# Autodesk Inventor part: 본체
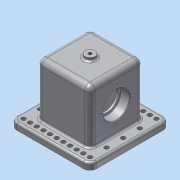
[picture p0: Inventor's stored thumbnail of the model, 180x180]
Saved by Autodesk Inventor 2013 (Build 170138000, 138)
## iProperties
Created: 2018-11
Part Number: 본체
Material: 알루미늄 6061
Document SubType Name: Modeling
Designer: dgall
Density: 2.71 g/cm^3
Mass: 1020.76 g
Surface Area: 777.082 cm^2
Volume: 376.663 cm^3
Author: dgall
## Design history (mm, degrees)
sketch "스케치1"
  geometry: L1 (0.533, -0.244)-(80.533, -0.244); L2 (80.533, -0.244)-(80.533, 79.756); L3 (80.533, 79.756)-(0.533, 79.756); L4 (0.533, 79.756)-(0.533, -0.244); 1 further point
  constraints: 8 end point, 2 parallel, 2 perpendicular, 1 horizontal
  dimensions: "d0" = 80 distance of L2.end L3.end
extrude "돌출1" new body sketch "스케치1" distance "d2" = 90; taper "d3" = 0 deg
sketch "스케치2"
  geometry: L1 (-0.533, -0.244)-(-0.533, 79.756) reference; L2 (-0.533, 79.756)-(-80.533, 79.756) reference; L3 (-100.533, -20.244)-(19.467, -20.244); L4 (19.467, -20.244)-(19.467, 99.756); L5 (19.467, 99.756)-(-100.533, 99.756); L6 (-100.533, 99.756)-(-100.533, -20.244); 5 further points
  constraints: 8 end point, 4 midpoint, 2 parallel, 2 perpendicular, 1 horizontal, 1 horizontal alignment, 1 vertical alignment
  dimensions: "d4" = 120 distance of L4.end L5.end
extrude "돌출2" join sketch "스케치2" distance "d6" = 10; taper "d7" = 0 deg
sketch "스케치3"
  geometry: L1 (19.467, -20.244)-(19.467, 99.756) reference; L2 (19.467, 99.756)-(-100.533, 99.756) reference; L3 (-63.533, 9.756)-(-17.533, 9.756); L4 (-17.533, 9.756)-(-17.533, 69.756); L5 (-17.533, 69.756)-(-63.533, 69.756); L6 (-63.533, 69.756)-(-63.533, 9.756); L7 (-100.533, -20.244)-(19.467, -20.244) reference; L8 (19.467, -20.244)-(19.467, 99.756) reference; L9 (19.467, 99.756)-(-100.533, 99.756) reference; L10 (-100.533, 99.756)-(-100.533, -20.244) reference; 5 further points
  constraints: 8 end point, 4 midpoint, 2 parallel, 1 horizontal, 1 horizontal alignment, 1 perpendicular, 1 vertical alignment
  dimensions: "d8" = 46 distance of L4.end L5.end; "d10" = 60 distance of L3.end L4.end
extrude "돌출3" cut sketch "스케치3" distance "d11" = 80; taper "d12" = 0 deg
sketch "스케치4"
  geometry: L1 (0, 0)-(0, 80) reference; L2 (80, 0)-(80, 80) reference; L3 (0, 80)-(80, 80) reference; L4 (0, 0)-(0, 80) reference; L5 (0, 0)-(80, 0) reference; L6 (90, 100)-(90, -20) reference; C1 r 20 at (42, 40); 2 further points
  constraints: 1 centre point, 1 horizontal alignment, 1 midpoint
  dimensions: "d13" = 48 distance from line of L6 C1.centre; "d14" = 40 diameter of C1
extrude "돌출4" cut sketch "스케치4" distance "d15" = 14; taper "d16" = 0 deg
sketch "스케치5"
  geometry: C1 r 20 at (0, 0) reference; C2 r 16.5 at (0, 0); 1 further point
  constraints: 1 centre point, 1 coincident
  dimensions: "d17" = 33 diameter of C2
extrude "돌출5" cut sketch "스케치5" distance "d19" = 17; taper "d20" = 0 deg
node "작업 평면1"
sketch "스케치6"
  geometry: L1 (0.533, -0.244)-(80.533, -0.244) reference; L2 (80.533, -0.244)-(80.533, 79.756) reference; L3 (80.533, 79.756)-(0.533, 79.756) reference; L4 (0.533, 79.756)-(0.533, -0.244) reference; C1 r 7.5 at (40.533, 39.756); 3 further points
  constraints: 2 midpoint, 1 centre point, 1 horizontal alignment, 1 vertical alignment
  dimensions: "d22" = 15 diameter of C1
extrude "돌출6" join sketch "스케치6" stored distance "d24" = 17; taper "d25" = 0 deg
node "작업 평면2"
fillet "모깎기1" dims "d26" = 10
sketch "스케치7"
  geometry: C1 r 3.3 at (-9.467, 89.756); A1 r 10 centre (-9.467, 89.756) between (-9.467, 99.756) and (-19.467, 89.756) reference; 1 further point
  constraints: 1 centre point, 1 coincident
  dimensions: "d27" = 6.6 diameter of C1
extrude "돌출7" cut sketch "스케치7" distance "d30" = 17; taper "d31" = 0 deg
node "작업 평면3"
fillet "모깎기2" dims "d38" = 8
fillet "모깎기3" dims "d39" = 3
fillet "모깎기4" dims "d40" = 3
hole "구멍1" diameter "d43" = 4.917; stored, may be unused: countersink angle "d47" = 90 deg, drill point angle "d49" = 118 deg; dims "d41" = 10, "d42" = 10, "d44" = 6, "d45" = 4, "d46" = 2, "d48" = 8
sketch "스케치8" dims "d50" = 52
  geometry: C1 r 20 at (-34, 32) reference; 3 further points
  constraints: 2 horizontal alignment, 1 coincident, 2 other
hole "구멍2" sketch "스케치8" at (-8, 32) diameter "d52" = 3.242; stored, may be unused: countersink angle "d56" = 90 deg, drill point angle "d58" = 118 deg; dims "d53" = 8, "d54" = 4, "d55" = 2, "d57" = 10
node "작업 평면4"
sketch "스케치9"
  geometry: L1 (-18, 82)-(82, 82) reference; L2 (0, 69)-(64, 69) reference; L3 (0, 0)-(0, 69) reference; L4 (64, 0)-(0, 0) reference; L5 (64, 69)-(64, 0) reference; 3 further points
  constraints: 1 midpoint, 1 vertical alignment, 1 other
  dimensions: "d63" = 48 distance from line of L1 point (32, 34)
feature "엠보싱1" sketch "스케치9" dims "d0" = 80, "d64" = 0.5, "d65" = 0
fillet "모깎기5" dims "d66" = 3
fillet "모깎기6" dims "d67" = 0.6
chamfer "모따기1" distance "d68" = 1; stored, may be unused: second distance "d69" = 2, angle "d70" = 45 deg
node "솔리드1"
mirror "대칭1"
pattern_linear "직사각형 패턴1" dims "d34" = 10
mirror "대칭2"
pattern_linear "직사각형 패턴2" dims "d37" = 25
mirror "대칭3"
pattern_circular "원형 패턴1" dims angle "d60" = 360 deg
mirror "대칭4"
node "투영된 루프1"
node "투영된 루프2"
node "투영된 루프3"
node "투영된 루프4"
other parameters: "d21" = -95
